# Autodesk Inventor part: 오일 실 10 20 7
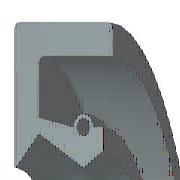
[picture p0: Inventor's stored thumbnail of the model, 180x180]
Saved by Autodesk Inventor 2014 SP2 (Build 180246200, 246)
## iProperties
IsCustomPart: 1
Created: 2012-02
Part Number: 오일 실 10 20 7
Material: 고무
Description: 오일-실
Document SubType Name: Modeling
Standard: KS B 2804
Designer: mduedu
Standards Organization: KS
Language: ko-KR
Size Designation: D - 10 20 7
Categories: <MemberInstance><Categories><Category DisplayName="샤프트 부품" InternalName="7f7aeb1f-a693-4053-b835-cee3144e0d98" Mnemonic="SHFT"><Category DisplayName="실링" Intern
Density: 0.93 g/cm^3
Appearance: 고무 - 검은색 - 버전 1.1
Author: mduedu
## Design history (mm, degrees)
revolve "본체" stored, may be unused: angle "d17" = 90 deg
revolve "스프링1" stored, may be unused: angle "d18" = 90 deg
body "Solid1"
sketch "스케치1"
  geometry: L1 (0, 10)-(7, 10); L2 (7, 8.25)-(1.75, 8.25); L3 (1.75, 6.75)-(4.9, 5); L4 (4.9, 5)-(0, 5); L5 (0, 0)-(9.586, 0) reference; L6 (4.9, 5)-(6.3, 5.875); L7 (0, 18)-(0, -3) reference; L8 (-1.941, 0)-(11.507, 0) reference; L9 (4.2, 7.1)-(1.75, 7.59); L10 (1.75, 7.59)-(1.75, 8.25); L11 (0, 10)-(0, 5.088); L12 (4.9, 5)-(0, 5); L13 (1.75, 6.75)-(0.152, 5.028); L14 (7, 10)-(7, 8.25); L15 (5.6, 7.1)-(6.3, 7.1); L16 (6.3, 7.1)-(6.3, 5.875); C1 r 0.455 at (4.9, 7.1); A1 r 0.7 centre (4.9, 7.1) between (5.6, 7.1) and (4.2, 7.1); A2 r 0.088 centre (0.088, 5.088) between (0, 5.088) and (0.152, 5.028); 1 further point
  constraints: 28 end point, 5 horizontal alignment, 5 point on line, 4 point on circle, 4 vertical alignment, 3 centre point, 3 tangent, 2 collinear, 2 horizontal, 2 perpendicular, 1 coincident, 1 parallel
  dimensions: "d0" = 20 diameter of L1 L5 (= SD2); "d1" = 1.75 distance of L1.end L2.start (= SD); "d2" = 0.91 diameter of C1 (= SPDI); "d3" = 1.4 diameter of A1 (= SPDA); "d4" = 10 diameter of L3.end L5 (= NND); "d5" = 13.5 diameter of L3.start L5 (= TKDM); "d7" = 15.18 diameter of L9.end L5 (= TKDM + 0.24 x SWDT); "d8" = 1.75 distance between parallel lines of L11 L10 (= SD); "d9" = 4.9 distance from line of L11 C1.centre (= SPDST); "d10" = 14.2 diameter of C1.centre L5 (= HLDM); "d11" = 0.0875 radius of A2 (= 0.25 x LAB); "d12" = 6.3 distance between parallel lines of L11 L16 (= SDI); "d13" = 11.75 diameter of L6.end L5 (= ABDM); "d14" = 7 distance from line of L11 L1.end (= SWDT)
fillet "모깎기1" dims "d6" = 0.3 (= RR)
other parameters: "SD2" = 20 [user parameter; used in 1 equation term], "SWDT" = 7 [user parameter; used in 2 equation terms], "RR" = 0.3 [user parameter; used in 1 equation term], "SD" = 1.75 [user parameter; used in 2 equation terms], "NND" = 10 [user parameter; used in 1 equation term], "SPDA" = 1.4 [user parameter; used in 1 equation term], "SPDI" = 0.91 [user parameter; used in 1 equation term], "TKDM" = 13.5 [user parameter; used in 2 equation terms], "HLDM" = 14.2 [user parameter; used in 1 equation term], "ABDM" = 11.75 [user parameter; used in 1 equation term], "SDI" = 6.3 [user parameter; used in 1 equation term], "SPDST" = 4.9 [user parameter; used in 1 equation term], "LAB" = 0.35 [user parameter; used in 1 equation term], "d15" = 0, "d16" = 0, "d19" = 0
